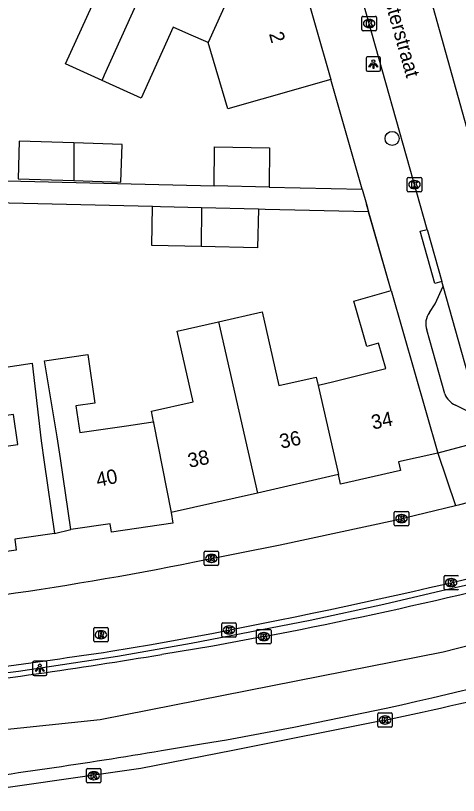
# Model space of a CAD drawing. Extents: x 161845 to 162341, y 381620 to 382158.
# Drawn here: x 162187.5 to 162218.3, y 381622.7 to 381677 of the extents above; entities that cross this region are included whole.
import ezdxf

# ---------------------------------------------------------------- set-up
doc = ezdxf.new("R2010")
doc.units = 0
for name, color, linetype in [('IMGEO_Boom', 7, 'Continuous'), ('IMGEO_Hek', 7, 'Continuous'), ('IMGEO_Kolk', 7, 'Continuous'), ('IMGEO_Lichtpunt', 7, 'Continuous'), ('IMGEO_Muur', 7, 'Continuous'), ('IMGEO_Openbare_ruimte_label', 7, 'Continuous'), ('IMGEO_Pand', 7, 'Continuous'), ('IMGEO_Pand_nummerreeks', 7, 'Continuous'), ('IMGEO_Rijbaan_lokaal_open', 7, 'Continuous'), ('IMGEO_Rijbaan_regionaal_gesloten', 7, 'Continuous'), ('IMGEO_Rioolput', 7, 'Continuous'), ('IMGEO_Voetpad_open', 7, 'Continuous')]:
    doc.layers.add(name, color=color, linetype=linetype)

msp = doc.modelspace()

# ---------------------------------------------------------------- linework, layer by layer
at = {"layer": 'IMGEO_Boom'}
msp.add_circle((162213.711, 381668.44), 0.489, dxfattribs=at)
at = {"layer": 'IMGEO_Hek'}
msp.add_lwpolyline([(162266.331, 381651.929), (162261.152, 381649.927), (162250.04, 381646.074), (162241.823, 381643.497), (162233.545, 381641.12), (162229.612, 381640.011), (162225.666, 381638.966), (162220.873, 381637.787), (162217.165, 381636.942), (162213.136, 381635.998), (162208.014, 381634.881), (162199.733, 381633.272), (162194.605, 381632.38), (162187.696, 381631.333), (162181.837, 381630.583), (162175.425, 381629.906), (162170.79, 381629.51), (162167.399, 381629.27), (162161.318, 381628.942), (162155.604, 381628.756), (162151.691, 381628.719), (162146.625, 381628.693)], dxfattribs=at)
at = {"layer": 'IMGEO_Kolk'}
for p, q in [((162211.689, 381676.94), (162212.541, 381676.94)), ((162211.614, 381676.014), (162211.614, 381676.866)), ((162212.102, 381676.72), (162212.127, 381676.72)), ((162212.615, 381676.866), (162212.615, 381676.014)), ((162212.541, 381675.94), (162211.689, 381675.94)), ((162212.125, 381676.16), (162212.1, 381676.16)), ((162214.768, 381664.803), (162214.768, 381665.655)), ((162214.843, 381665.729), (162215.695, 381665.729)), ((162215.256, 381665.509), (162215.281, 381665.509)), ((162215.769, 381665.655), (162215.769, 381664.803)), ((162215.279, 381664.949), (162215.254, 381664.949)), ((162215.695, 381664.729), (162214.843, 381664.729)), ((162213.865, 381641.548), (162213.865, 381642.4)), ((162213.94, 381642.474), (162214.792, 381642.474)), ((162214.353, 381642.254), (162214.378, 381642.254)), ((162214.866, 381642.4), (162214.866, 381641.548)), ((162214.376, 381641.694), (162214.351, 381641.694)), ((162214.792, 381641.474), (162213.94, 381641.474)), ((162200.632, 381638.776), (162200.632, 381639.628)), ((162200.707, 381639.702), (162201.559, 381639.702)), ((162201.12, 381639.482), (162201.145, 381639.482)), ((162201.633, 381639.628), (162201.633, 381638.776)), ((162201.143, 381638.922), (162201.118, 381638.922)), ((162201.559, 381638.702), (162200.707, 381638.702)), ((162217.324, 381637.09), (162217.324, 381637.942)), ((162217.399, 381638.016), (162218.251, 381638.016)), ((162217.812, 381637.796), (162217.837, 381637.796)), ((162218.251, 381637.016), (162217.399, 381637.016)), ((162217.835, 381637.236), (162217.81, 381637.236)), ((162201.859, 381633.797), (162201.859, 381634.649)), ((162201.934, 381634.723), (162202.786, 381634.723)), ((162202.86, 381634.649), (162202.86, 381633.797)), ((162202.347, 381634.503), (162202.372, 381634.503)), ((162204.281, 381633.335), (162204.281, 381634.187)), ((162204.356, 381634.261), (162205.208, 381634.261)), ((162204.769, 381634.041), (162204.794, 381634.041)), ((162205.282, 381634.187), (162205.282, 381633.335)), ((162202.786, 381633.723), (162201.934, 381633.723)), ((162202.37, 381633.943), (162202.345, 381633.943)), ((162204.792, 381633.481), (162204.767, 381633.481)), ((162205.208, 381633.261), (162204.356, 381633.261)), ((162212.719, 381627.526), (162212.719, 381628.378)), ((162212.794, 381628.452), (162213.646, 381628.452)), ((162213.207, 381628.232), (162213.232, 381628.232)), ((162213.72, 381628.378), (162213.72, 381627.526)), ((162213.23, 381627.672), (162213.205, 381627.672)), ((162213.646, 381627.452), (162212.794, 381627.452)), ((162192.441, 381623.646), (162192.441, 381624.498)), ((162192.516, 381624.572), (162193.368, 381624.572)), ((162192.929, 381624.352), (162192.954, 381624.352)), ((162193.442, 381624.498), (162193.442, 381623.646)), ((162192.952, 381623.792), (162192.927, 381623.792)), ((162193.368, 381623.572), (162192.516, 381623.572))]:
    msp.add_line(p, q, dxfattribs=at)
for points in [[(162211.689, 381676.94), (162212.541, 381676.94)], [(162211.614, 381676.014), (162211.614, 381676.866)], [(162211.935, 381676.64), (162212.058, 381676.64), (162212.058, 381676.489), (162212.188, 381676.64), (162212.352, 381676.64), (162212.206, 381676.489), (162212.359, 381676.24), (162212.207, 381676.24), (162212.122, 381676.404), (162212.058, 381676.337), (162212.058, 381676.24), (162211.935, 381676.24), (162211.935, 381676.64)], [(162212.615, 381676.866), (162212.615, 381676.014)], [(162212.541, 381675.94), (162211.689, 381675.94)], [(162214.768, 381664.803), (162214.768, 381665.655)], [(162214.843, 381665.729), (162215.695, 381665.729)], [(162215.769, 381665.655), (162215.769, 381664.803)], [(162215.089, 381665.429), (162215.212, 381665.429), (162215.212, 381665.278), (162215.342, 381665.429), (162215.506, 381665.429), (162215.36, 381665.278), (162215.513, 381665.029), (162215.361, 381665.029), (162215.276, 381665.193), (162215.212, 381665.126), (162215.212, 381665.029), (162215.089, 381665.029), (162215.089, 381665.429)], [(162215.695, 381664.729), (162214.843, 381664.729)], [(162213.865, 381641.548), (162213.865, 381642.4)], [(162213.94, 381642.474), (162214.792, 381642.474)], [(162214.186, 381642.174), (162214.309, 381642.174), (162214.309, 381642.023), (162214.439, 381642.174), (162214.603, 381642.174), (162214.457, 381642.023), (162214.61, 381641.774), (162214.458, 381641.774), (162214.373, 381641.938), (162214.309, 381641.871), (162214.309, 381641.774), (162214.186, 381641.774), (162214.186, 381642.174)], [(162214.866, 381642.4), (162214.866, 381641.548)], [(162214.792, 381641.474), (162213.94, 381641.474)], [(162200.632, 381638.776), (162200.632, 381639.628)], [(162200.707, 381639.702), (162201.559, 381639.702)], [(162201.633, 381639.628), (162201.633, 381638.776)], [(162200.953, 381639.402), (162201.076, 381639.402), (162201.076, 381639.251), (162201.206, 381639.402), (162201.37, 381639.402), (162201.224, 381639.251), (162201.377, 381639.002), (162201.225, 381639.002), (162201.14, 381639.166), (162201.076, 381639.099), (162201.076, 381639.002), (162200.953, 381639.002), (162200.953, 381639.402)], [(162201.559, 381638.702), (162200.707, 381638.702)], [(162217.324, 381637.09), (162217.324, 381637.942)], [(162217.399, 381638.016), (162218.251, 381638.016)], [(162217.645, 381637.716), (162217.768, 381637.716), (162217.768, 381637.565), (162217.898, 381637.716), (162218.062, 381637.716), (162217.916, 381637.565), (162218.069, 381637.316), (162217.917, 381637.316), (162217.832, 381637.48), (162217.768, 381637.413), (162217.768, 381637.316), (162217.645, 381637.316), (162217.645, 381637.716)], [(162218.251, 381637.016), (162217.399, 381637.016)], [(162201.859, 381633.797), (162201.859, 381634.649)], [(162201.934, 381634.723), (162202.786, 381634.723)], [(162202.86, 381634.649), (162202.86, 381633.797)], [(162202.18, 381634.423), (162202.303, 381634.423), (162202.303, 381634.272), (162202.433, 381634.423), (162202.597, 381634.423), (162202.451, 381634.272), (162202.604, 381634.023), (162202.452, 381634.023), (162202.367, 381634.187), (162202.303, 381634.12), (162202.303, 381634.023), (162202.18, 381634.023), (162202.18, 381634.423)], [(162204.281, 381633.335), (162204.281, 381634.187)], [(162204.356, 381634.261), (162205.208, 381634.261)], [(162205.282, 381634.187), (162205.282, 381633.335)], [(162202.786, 381633.723), (162201.934, 381633.723)], [(162204.602, 381633.961), (162204.725, 381633.961), (162204.725, 381633.81), (162204.855, 381633.961), (162205.019, 381633.961), (162204.873, 381633.81), (162205.026, 381633.561), (162204.874, 381633.561), (162204.789, 381633.725), (162204.725, 381633.658), (162204.725, 381633.561), (162204.602, 381633.561), (162204.602, 381633.961)], [(162205.208, 381633.261), (162204.356, 381633.261)], [(162212.719, 381627.526), (162212.719, 381628.378)], [(162212.794, 381628.452), (162213.646, 381628.452)], [(162213.04, 381628.152), (162213.163, 381628.152), (162213.163, 381628.001), (162213.293, 381628.152), (162213.457, 381628.152), (162213.311, 381628.001), (162213.464, 381627.752), (162213.312, 381627.752), (162213.227, 381627.916), (162213.163, 381627.849), (162213.163, 381627.752), (162213.04, 381627.752), (162213.04, 381628.152)], [(162213.72, 381628.378), (162213.72, 381627.526)], [(162213.646, 381627.452), (162212.794, 381627.452)], [(162192.441, 381623.646), (162192.441, 381624.498)], [(162192.516, 381624.572), (162193.368, 381624.572)], [(162192.762, 381624.272), (162192.885, 381624.272), (162192.885, 381624.121), (162193.015, 381624.272), (162193.179, 381624.272), (162193.033, 381624.121), (162193.186, 381623.872), (162193.034, 381623.872), (162192.949, 381624.036), (162192.885, 381623.969), (162192.885, 381623.872), (162192.762, 381623.872), (162192.762, 381624.272)], [(162193.442, 381624.498), (162193.442, 381623.646)], [(162193.368, 381623.572), (162192.516, 381623.572)]]:
    msp.add_lwpolyline(points, dxfattribs=at)
for centre, start, end in [((162211.691, 381676.864), 91.552, 178.448), ((162211.691, 381676.864), 91.552, 178.448), ((162212.539, 381676.864), 1.552, 88.448), ((162212.539, 381676.864), 1.552, 88.448), ((162211.691, 381676.016), 181.552, 268.448), ((162211.691, 381676.016), 181.552, 268.448), ((162212.539, 381676.016), 271.552, 358.448), ((162212.539, 381676.016), 271.552, 358.448), ((162214.845, 381665.653), 91.552, 178.448), ((162214.845, 381665.653), 91.552, 178.448), ((162215.693, 381665.653), 1.552, 88.448), ((162215.693, 381665.653), 1.552, 88.448), ((162214.845, 381664.805), 181.552, 268.448), ((162214.845, 381664.805), 181.552, 268.448), ((162215.693, 381664.805), 271.552, 358.448), ((162215.693, 381664.805), 271.552, 358.448), ((162213.942, 381642.398), 91.552, 178.448), ((162213.942, 381642.398), 91.552, 178.448), ((162214.79, 381642.398), 1.552, 88.448), ((162214.79, 381642.398), 1.552, 88.448), ((162213.942, 381641.55), 181.552, 268.448), ((162213.942, 381641.55), 181.552, 268.448), ((162214.79, 381641.55), 271.552, 358.448), ((162214.79, 381641.55), 271.552, 358.448), ((162200.709, 381639.626), 91.552, 178.448), ((162200.709, 381639.626), 91.552, 178.448), ((162201.557, 381639.626), 1.552, 88.448), ((162201.557, 381639.626), 1.552, 88.448), ((162200.709, 381638.778), 181.552, 268.448), ((162200.709, 381638.778), 181.552, 268.448), ((162201.557, 381638.778), 271.552, 358.448), ((162201.557, 381638.778), 271.552, 358.448), ((162217.401, 381637.94), 91.552, 178.448), ((162217.401, 381637.94), 91.552, 178.448), ((162218.249, 381637.94), 1.552, 88.448), ((162218.249, 381637.94), 1.552, 88.448), ((162217.401, 381637.092), 181.552, 268.448), ((162217.401, 381637.092), 181.552, 268.448), ((162218.249, 381637.092), 271.552, 358.448), ((162218.249, 381637.092), 271.552, 358.448), ((162201.936, 381634.647), 91.552, 178.448), ((162201.936, 381634.647), 91.552, 178.448), ((162202.784, 381634.647), 1.552, 88.448), ((162202.784, 381634.647), 1.552, 88.448), ((162204.358, 381634.185), 91.552, 178.448), ((162204.358, 381634.185), 91.552, 178.448), ((162205.206, 381634.185), 1.552, 88.448), ((162205.206, 381634.185), 1.552, 88.448), ((162201.936, 381633.799), 181.552, 268.448), ((162201.936, 381633.799), 181.552, 268.448), ((162202.784, 381633.799), 271.552, 358.448), ((162202.784, 381633.799), 271.552, 358.448), ((162204.358, 381633.337), 181.552, 268.448), ((162204.358, 381633.337), 181.552, 268.448), ((162205.206, 381633.337), 271.552, 358.448), ((162205.206, 381633.337), 271.552, 358.448), ((162212.796, 381628.376), 91.552, 178.448), ((162212.796, 381628.376), 91.552, 178.448), ((162213.644, 381628.376), 1.552, 88.448), ((162213.644, 381628.376), 1.552, 88.448), ((162212.796, 381627.528), 181.552, 268.448), ((162212.796, 381627.528), 181.552, 268.448), ((162213.644, 381627.528), 271.552, 358.448), ((162213.644, 381627.528), 271.552, 358.448), ((162192.518, 381624.496), 91.552, 178.448), ((162192.518, 381624.496), 91.552, 178.448), ((162193.366, 381624.496), 1.552, 88.448), ((162193.366, 381624.496), 1.552, 88.448), ((162192.518, 381623.648), 181.552, 268.448), ((162192.518, 381623.648), 181.552, 268.448), ((162193.366, 381623.648), 271.552, 358.448), ((162193.366, 381623.648), 271.552, 358.448)]:
    msp.add_arc(centre, 0.0765, start, end, dxfattribs=at)
for centre, major_axis, ratio, start_param, end_param in [((162212.101, 381676.44), (-0.387, 0.002), 0.722429, 4.712389, 7.853982), ((162212.126, 381676.44), (-0.39, 0.002), 0.717154, 1.570796, 4.712389), ((162215.255, 381665.229), (-0.387, 0.002), 0.722429, 4.712389, 7.853982), ((162215.28, 381665.229), (-0.39, 0.002), 0.717154, 1.570796, 4.712389), ((162214.352, 381641.974), (-0.387, 0.002), 0.722429, 4.712389, 7.853982), ((162214.377, 381641.974), (-0.39, 0.002), 0.717154, 1.570796, 4.712389), ((162201.119, 381639.202), (-0.387, 0.002), 0.722429, 4.712389, 7.853982), ((162201.144, 381639.202), (-0.39, 0.002), 0.717154, 1.570796, 4.712389), ((162217.811, 381637.516), (-0.387, 0.002), 0.722429, 4.712389, 7.853982), ((162217.836, 381637.516), (-0.39, 0.002), 0.717154, 1.570796, 4.712389), ((162202.346, 381634.223), (-0.387, 0.002), 0.722429, 4.712389, 7.853982), ((162202.371, 381634.223), (-0.39, 0.002), 0.717154, 1.570796, 4.712389), ((162204.768, 381633.761), (-0.387, 0.002), 0.722429, 4.712389, 7.853982), ((162204.793, 381633.761), (-0.39, 0.002), 0.717154, 1.570796, 4.712389), ((162213.206, 381627.952), (-0.387, 0.002), 0.722429, 4.712389, 7.853982), ((162213.231, 381627.952), (-0.39, 0.002), 0.717154, 1.570796, 4.712389), ((162192.928, 381624.072), (-0.387, 0.002), 0.722429, 4.712389, 7.853982), ((162192.953, 381624.072), (-0.39, 0.002), 0.717154, 1.570796, 4.712389)]:
    msp.add_ellipse(centre, major_axis=major_axis, ratio=ratio, start_param=start_param, end_param=end_param, dxfattribs=at)
at = {"layer": 'IMGEO_Lichtpunt'}
for p, q in [((162211.911, 381674.018), (162211.911, 381673.211)), ((162211.911, 381674.018), (162211.911, 381673.211)), ((162212.813, 381674.113), (162212.005, 381674.113)), ((162212.813, 381674.113), (162212.005, 381674.113)), ((162212.907, 381673.211), (162212.907, 381674.018)), ((162212.907, 381673.211), (162212.907, 381674.018)), ((162212.005, 381673.117), (162212.813, 381673.117)), ((162212.005, 381673.117), (162212.813, 381673.117)), ((162188.691, 381631.956), (162188.691, 381631.149)), ((162188.691, 381631.956), (162188.691, 381631.149)), ((162189.593, 381632.051), (162188.785, 381632.051)), ((162189.593, 381632.051), (162188.785, 381632.051)), ((162189.687, 381631.149), (162189.687, 381631.956)), ((162189.687, 381631.149), (162189.687, 381631.956)), ((162188.785, 381631.055), (162189.593, 381631.055)), ((162188.785, 381631.055), (162189.593, 381631.055))]:
    msp.add_line(p, q, dxfattribs=at)
for points in [[(162212.285, 381673.682), (162212.324, 381673.654), (162212.136, 381673.392), (162212.098, 381673.419), (162212.285, 381673.682)], [(162212.387, 381673.634), (162212.434, 381673.634), (162212.434, 381673.312), (162212.387, 381673.312), (162212.387, 381673.634)], [(162212.497, 381673.654), (162212.535, 381673.681), (162212.722, 381673.419), (162212.683, 381673.391), (162212.497, 381673.654)], [(162189.065, 381631.62), (162189.104, 381631.592), (162188.916, 381631.33), (162188.878, 381631.357), (162189.065, 381631.62)], [(162189.167, 381631.572), (162189.214, 381631.572), (162189.214, 381631.25), (162189.167, 381631.25), (162189.167, 381631.572)], [(162189.277, 381631.592), (162189.315, 381631.619), (162189.502, 381631.357), (162189.463, 381631.329), (162189.277, 381631.592)]]:
    msp.add_lwpolyline(points, dxfattribs=at)
for centre in [(162212.41, 381673.816), (162189.19, 381631.754)]:
    msp.add_circle(centre, 0.0994, dxfattribs=at)
for centre, start, end in [((162212.005, 381674.018), 90, 180), ((162212.005, 381674.018), 90, 180), ((162212.813, 381674.018), 0, 90), ((162212.813, 381674.018), 0, 90), ((162212.005, 381673.211), 180, 270), ((162212.005, 381673.211), 180, 270), ((162212.813, 381673.211), 270, 0), ((162212.813, 381673.211), 270, 360), ((162188.785, 381631.956), 90, 180), ((162188.785, 381631.956), 90, 180), ((162189.593, 381631.956), 0, 90), ((162189.593, 381631.956), 0, 90), ((162188.785, 381631.149), 180, 270), ((162188.785, 381631.149), 180, 270), ((162189.593, 381631.149), 270, 0), ((162189.593, 381631.149), 270, 360)]:
    msp.add_arc(centre, 0.0946, start, end, dxfattribs=at)
at = {"layer": 'IMGEO_Muur'}
for points in [[(162211.629, 381664.907), (162209.452, 381672.542)], [(162211.97, 381663.71), (162211.928, 381663.857)], [(162213.638, 381657.855), (162211.97, 381663.71)]]:
    msp.add_lwpolyline(points, dxfattribs=at)
at = {"layer": 'IMGEO_Pand'}
for points in [[(162193.523, 381672.479), (162193.693, 381672.857), (162198.726, 381684.025)], [(162203.869, 381681.706), (162201.019, 381675.369), (162200.911, 381675.128)], [(162207.271, 381680.172), (162209.452, 381672.542)], [(162193.523, 381672.479), (162190.982, 381673.625), (162193.196, 381678.533), (162190.591, 381679.708)], [(162200.911, 381675.128), (162199.554, 381675.698), (162198.461, 381676.191), (162196.236, 381671.255), (162193.523, 381672.479)], [(162209.452, 381672.542), (162204.645, 381671.168), (162202.284, 381670.493), (162200.911, 381675.128)], [(162191.561, 381668.127), (162187.763, 381668.259), (162187.671, 381665.637), (162191.564, 381665.502)], [(162191.561, 381668.127), (162191.564, 381665.502)], [(162191.564, 381665.502), (162194.824, 381665.388), (162194.915, 381668.01), (162191.561, 381668.127)], [(162201.323, 381665.149), (162201.341, 381667.859), (162205.169, 381667.776), (162205.151, 381665.056)], [(162205.151, 381665.056), (162201.323, 381665.149)], [(162200.431, 381660.91), (162196.979, 381660.994), (162197.044, 381663.693)], [(162200.432, 381663.611), (162197.593, 381663.68), (162197.044, 381663.693)], [(162200.432, 381663.611), (162200.431, 381660.91)], [(162204.412, 381663.514), (162204.347, 381660.815), (162200.431, 381660.91)], [(162204.412, 381663.514), (162200.432, 381663.611)], [(162208.561, 381651.251), (162208.686, 381651.281), (162209.568, 381651.501), (162213.264, 381652.425), (162212.76, 381654.181), (162211.952, 381653.949), (162211.045, 381657.111), (162213.638, 381657.855)], [(162213.638, 381657.855), (162216.887, 381646.538)], [(162201.622, 381655.682), (162204.663, 381656.373), (162205.831, 381651.236), (162208.43, 381651.826), (162208.561, 381651.251)], [(162197.097, 381648.704), (162196.953, 381649.443), (162199.863, 381650.104), (162198.744, 381655.028), (162201.622, 381655.682)], [(162201.622, 381655.682), (162201.738, 381655.172), (162204.337, 381643.756)], [(162191.344, 381641.208), (162190.629, 381646.157), (162190.387, 381647.667), (162189.516, 381652.954), (162192.542, 381653.391), (162193.029, 381650.018), (162191.703, 381649.827), (162191.972, 381647.964), (162195.219, 381648.433), (162196.911, 381648.677), (162197.097, 381648.704)], [(162182.533, 381646.399), (162182.672, 381646.419), (162183.599, 381646.553), (162187.664, 381647.139), (162187.362, 381649.229), (162185.9, 381649.018), (162185.423, 381652.319), (162188.649, 381652.784), (162189.282, 381647.391), (162189.493, 381645.896), (162190.207, 381640.947)], [(162208.561, 381651.251), (162209.978, 381645.034)], [(162197.097, 381648.704), (162197.109, 381648.644), (162198.335, 381642.391)], [(162216.887, 381646.538), (162214.157, 381645.917), (162214.292, 381645.325), (162210.127, 381644.378), (162209.978, 381645.034)], [(162209.978, 381645.034), (162204.337, 381643.756)], [(162204.337, 381643.756), (162198.335, 381642.391)], [(162198.335, 381642.391), (162198.442, 381641.649), (162194.18, 381641.034), (162194.097, 381641.605), (162191.344, 381641.208)], [(162190.207, 381640.947), (162187.44, 381640.547), (162187.55, 381639.782), (162183.361, 381639.177), (162183.28, 381639.742)]]:
    msp.add_lwpolyline(points, dxfattribs=at)
at = {"layer": 'IMGEO_Rijbaan_lokaal_open'}
for points in [[(162215.556, 381681.205), (162219.035, 381668.723)], [(162216.148, 381662.111), (162211.114, 381680.002)], [(162216.148, 381662.111), (162217.172, 381658.471)], [(162217.261, 381658.154), (162217.172, 381658.471)], [(162220.068, 381648.178), (162217.261, 381658.154)], [(162218.121, 381642.892), (162218.428, 381642.967), (162228.937, 381645.699), (162229.134, 381645.75), (162236.593, 381647.788), (162241.048, 381649.166)], [(162199.956, 381638.956), (162205.924, 381640.149), (162213.893, 381641.857), (162218.121, 381642.892)], [(162194.125, 381632.738), (162196.966, 381633.218), (162201.287, 381634.009), (162204.617, 381634.678)]]:
    msp.add_lwpolyline(points, dxfattribs=at)
for centre, radius, start, end in [((162137.649, 381978.348), 350.134, 281.02648, 287.29289), ((162152.698, 381874.845), 240.576, 274.44717, 281.32872), ((162125.277, 382092.031), 464.424, 276.5055, 278.52512)]:
    msp.add_arc(centre, radius, start, end, dxfattribs=at)
at = {"layer": 'IMGEO_Rijbaan_regionaal_gesloten'}
for points in [[(162065.762, 381627.224), (162074.598, 381626.568), (162101.225, 381625.613), (162133.688, 381624.885), (162151.965, 381624.703), (162167.196, 381625.249), (162193.384, 381627.978), (162217.254, 381632.709), (162234.44, 381637.075), (162251.353, 381642.169), (162267.176, 381648.082), (162286.544, 381657.725), (162299.911, 381665.73), (162311.76, 381673.667)], [(162204.779, 381633.759), (162201.221, 381633.098), (162197.674, 381632.511)], [(162197.654, 381625.82), (162200.575, 381626.313), (162202.178, 381626.577), (162206.862, 381627.445), (162213.304, 381628.78)], [(162213.216, 381627.95), (162202.615, 381625.821), (162196.222, 381624.571), (162183.072, 381622.703)]]:
    msp.add_lwpolyline(points, dxfattribs=at)
for centre, radius, start, end in [((162141.246, 381964.503), 336.79, 280.87362, 285.61919), ((162115.301, 382067.41), 449.445, 282.59478, 287.02725), ((162147.07, 381942.387), 321.319, 281.87964, 285.64064), ((162127.7, 382058.233), 431.434, 276.98858, 279.33403), ((162124.819, 382065.373), 445.546, 277.3365, 279.40852)]:
    msp.add_arc(centre, radius, start, end, dxfattribs=at)
at = {"layer": 'IMGEO_Rioolput'}
for p, q in [((162192.941, 381633.462), (162192.941, 381634.314)), ((162193.016, 381634.388), (162193.868, 381634.388)), ((162193.429, 381634.168), (162193.454, 381634.168)), ((162193.942, 381634.314), (162193.942, 381633.462)), ((162193.452, 381633.608), (162193.427, 381633.608)), ((162193.868, 381633.388), (162193.016, 381633.388))]:
    msp.add_line(p, q, dxfattribs=at)
for points in [[(162192.941, 381633.462), (162192.941, 381634.314)], [(162193.016, 381634.388), (162193.868, 381634.388)], [(162193.53, 381634.086), (162193.278, 381634.088), (162193.278, 381633.688)], [(162193.456, 381634.007), (162193.402, 381634.007), (162193.402, 381633.926)], [(162193.942, 381634.314), (162193.942, 381633.462)], [(162193.278, 381633.688), (162193.402, 381633.688), (162193.402, 381633.85), (162193.413, 381633.85)], [(162193.402, 381633.926), (162193.454, 381633.926)], [(162193.46, 381633.821), (162193.531, 381633.688), (162193.671, 381633.688), (162193.606, 381633.814)], [(162193.868, 381633.388), (162193.016, 381633.388)]]:
    msp.add_lwpolyline(points, dxfattribs=at)
for centre, radius, start, end in [((162193.018, 381634.312), 0.0765, 91.552, 178.448), ((162193.018, 381634.312), 0.0765, 91.552, 178.448), ((162193.462, 381633.911), 0.0964, 77.0061, 93.1865), ((162193.476, 381633.968), 0.0378, 276.6634, 79.6772), ((162193.529, 381633.976), 0.109, 350.3612, 89.416), ((162193.866, 381634.312), 0.0765, 1.552, 88.448), ((162193.866, 381634.312), 0.0765, 1.552, 88.448), ((162193.018, 381633.464), 0.0765, 181.552, 268.448), ((162193.018, 381633.464), 0.0765, 181.552, 268.448), ((162193.412, 381633.797), 0.0533, 26.0293, 88.6989), ((162193.438, 381634.115), 0.19, 274.7715, 282.9687), ((162193.527, 381633.976), 0.112, 277.5842, 350.9817), ((162193.511, 381633.761), 0.108, 29.5134, 73.7905), ((162193.866, 381633.464), 0.0765, 271.552, 358.448), ((162193.866, 381633.464), 0.0765, 271.552, 358.448)]:
    msp.add_arc(centre, radius, start, end, dxfattribs=at)
for centre, major_axis, ratio, start_param, end_param in [((162193.428, 381633.888), (-0.387, 0.002), 0.722429, 4.712389, 7.853982), ((162193.453, 381633.888), (-0.39, 0.002), 0.717154, 1.570796, 4.712389)]:
    msp.add_ellipse(centre, major_axis=major_axis, ratio=ratio, start_param=start_param, end_param=end_param, dxfattribs=at)
at = {"layer": 'IMGEO_Voetpad_open'}
for points in [[(162211.629, 381664.907), (162209.452, 381672.542)], [(162183.031, 381665.574), (162201.323, 381665.149)], [(162205.151, 381665.056), (162211.629, 381664.907)], [(162211.629, 381664.907), (162211.928, 381663.857), (162212.079, 381663.327)], [(162197.044, 381663.693), (162187.051, 381663.936), (162181.089, 381664.081), (162178.953, 381664.133), (162178.947, 381663.939)], [(162212.079, 381663.327), (162204.871, 381663.503), (162204.412, 381663.514)], [(162213.638, 381657.855), (162212.079, 381663.327)], [(162217.172, 381658.471), (162216.691, 381658.336), (162215.667, 381661.976), (162216.148, 381662.111)], [(162216.309, 381656.315), (162216.716, 381656.937), (162217.261, 381658.154)], [(162217.382, 381650.652), (162216.13, 381655.109)], [(162219.006, 381649.432), (162218.117, 381649.877)], [(162220.275, 381647.442), (162216.887, 381646.538)], [(162216.887, 381646.538), (162218.121, 381642.892)], [(162190.207, 381640.947), (162191.344, 381641.208)]]:
    msp.add_lwpolyline(points, dxfattribs=at)
for centre, radius, start, end in [((162217.335, 381655.546), 1.282, 143.1628, 199.9523), ((162218.721, 381651.186), 1.442, 201.7391, 245.2261)]:
    msp.add_arc(centre, radius, start, end, dxfattribs=at)

# ---------------------------------------------------------------- texts
at = {"layer": 'IMGEO_Openbare_ruimte_label'}
msp.add_text('Asterstraat', height=1, rotation=285.7879, dxfattribs=at).set_placement((162212.955, 381678.82))
at = {"layer": 'IMGEO_Pand_nummerreeks'}
for s, rotation, p in [('2', 285.9523, (162205.131, 381675.722)), ('34', 11.7857, (162212.371, 381648.17)), ('36', 11.7867, (162205.985, 381646.838)), ('38', 11.7857, (162199.601, 381645.505)), ('40', 11.7857, (162193.215, 381644.172))]:
    msp.add_text(s, height=1, rotation=rotation, dxfattribs=at).set_placement(p)

doc.saveas('drawing.dxf')
